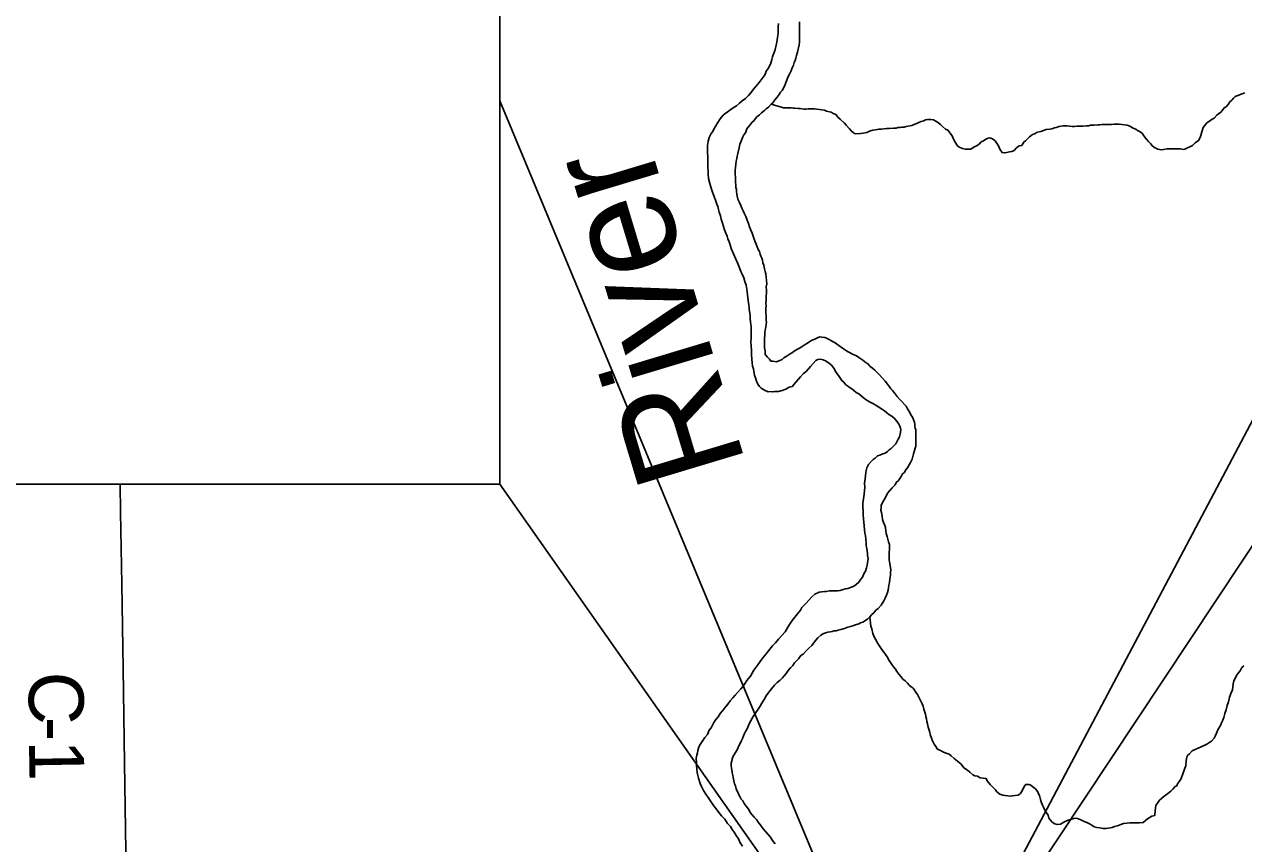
# Model space of a CAD drawing. Extents: x 0 to 34, y 0 to 22.
# Drawn here: x 5.328 to 6.59, y 17.212 to 18.059 of the extents above; entities that cross this region are included whole.
import ezdxf

# ---------------------------------------------------------------- set-up
doc = ezdxf.new("R2010")
doc.units = 0
for name, color, linetype in [('GM_X_County_Road', 7, 'Continuous'), ('GM_X_County_Road_Text', 7, 'Continuous'), ('GM_X_Major_River', 7, 'Continuous'), ('GM_X_Major_River_Text', 7, 'Continuous'), ('GM_X_Minor_River', 7, 'Continuous'), ('SH_Border', 7, 'Continuous')]:
    doc.layers.add(name, color=color, linetype=linetype)

msp = doc.modelspace()

# ---------------------------------------------------------------- linework, layer by layer
at = {"layer": 'GM_X_County_Road'}
msp.add_lwpolyline([(5.4268, 17.5835), (5.4273, 17.5548), (5.4287, 17.4801), (5.4301, 17.393), (5.4313, 17.2951), (5.4329, 17.2045), (5.4343, 17.1322), (5.4347, 17.045), (5.4352, 17.0104)], dxfattribs=at)
at = {"layer": 'GM_X_Major_River'}
for points in [[(6.1082, 18.06), (6.1079, 18.0569), (6.108, 18.0535), (6.108, 18.0504), (6.1077, 18.0478), (6.1074, 18.0455), (6.107, 18.0432), (6.1067, 18.0409), (6.106, 18.0375), (6.105, 18.0333), (6.1039, 18.0302), (6.1028, 18.0275), (6.1021, 18.0256), (6.1014, 18.0229), (6.1003, 18.0191), (6.0985, 18.0153), (6.097, 18.0126), (6.0956, 18.0107), (6.0949, 18.0084), (6.0934, 18.006), (6.0915, 18.0033), (6.0893, 18.0006), (6.0871, 17.9972), (6.0845, 17.9945), (6.0826, 17.9921), (6.0808, 17.9898), (6.0793, 17.9879), (6.0771, 17.9856), (6.0741, 17.9824), (6.0707, 17.9801), (6.0681, 17.9778), (6.0648, 17.975), (6.0614, 17.9727), (6.0528, 17.9668), (6.0509, 17.9652), (6.0479, 17.9614), (6.045, 17.9567), (6.0435, 17.9544), (6.042, 17.9521), (6.0402, 17.9483), (6.0387, 17.9463), (6.0376, 17.9444), (6.0365, 17.9421), (6.0355, 17.9383), (6.0351, 17.9364), (6.0348, 17.9337), (6.0349, 17.9311), (6.0349, 17.9288), (6.035, 17.9261), (6.0351, 17.9227), (6.0351, 17.9197), (6.0352, 17.9166)], [(6.0959, 17.7811), (6.0958, 17.7842), (6.0957, 17.7876), (6.0961, 17.791), (6.0955, 17.7978), (6.0951, 17.8012), (6.0946, 17.8035), (6.0938, 17.8065), (6.093, 17.8103), (6.0922, 17.8126), (6.0917, 17.8152), (6.0909, 17.8175), (6.0901, 17.8194), (6.0893, 17.8216), (6.0885, 17.8243), (6.0873, 17.8265), (6.0861, 17.8292), (6.0853, 17.8318), (6.0841, 17.8341), (6.0833, 17.8371), (6.0821, 17.8401), (6.0809, 17.8431), (6.0797, 17.8465), (6.0784, 17.8499), (6.0772, 17.8533), (6.076, 17.8567), (6.0744, 17.8605), (6.0728, 17.8639), (6.0716, 17.8665), (6.0704, 17.8691), (6.0692, 17.8718), (6.0676, 17.8755), (6.0664, 17.8785), (6.0656, 17.8816), (6.0652, 17.8838), (6.0647, 17.8861), (6.0647, 17.8884), (6.0643, 17.8903), (6.0642, 17.8937), (6.0638, 17.8956), (6.0637, 17.8979), (6.0637, 17.9013), (6.0636, 17.9039), (6.0636, 17.9062), (6.0635, 17.9081), (6.0638, 17.9115), (6.0641, 17.9146), (6.0645, 17.9176), (6.0652, 17.9203), (6.0655, 17.923), (6.0662, 17.9257), (6.0676, 17.9314), (6.0683, 17.9352), (6.0697, 17.9383), (6.0708, 17.941), (6.0715, 17.9429), (6.0726, 17.9448), (6.0741, 17.9471), (6.0755, 17.9513), (6.0785, 17.9548), (6.0811, 17.9579), (6.083, 17.9598), (6.0844, 17.9618), (6.0859, 17.9637), (6.0885, 17.9657), (6.0908, 17.9676), (6.0938, 17.97), (6.0956, 17.9719), (6.0979, 17.9735), (6.1009, 17.9766), (6.1027, 17.9785), (6.1046, 17.9812), (6.1068, 17.9839), (6.109, 17.9866), (6.1105, 17.9889), (6.112, 17.9909), (6.1138, 17.994), (6.1153, 17.997), (6.116, 17.9989), (6.1171, 18.0016), (6.1181, 18.0047), (6.1196, 18.0078), (6.1211, 18.0104), (6.1221, 18.0131), (6.1229, 18.015), (6.124, 18.017), (6.1247, 18.0197), (6.1254, 18.0219), (6.1261, 18.0242), (6.1268, 18.0269), (6.1279, 18.0304), (6.1296, 18.038), (6.1299, 18.0407), (6.1302, 18.0445), (6.1301, 18.0483), (6.13, 18.0528), (6.13, 18.0559), (6.1299, 18.0589), (6.1299, 18.0619)], [(6.0352, 17.9166), (6.0352, 17.9136), (6.0353, 17.9109), (6.0354, 17.9075), (6.0354, 17.9041), (6.0359, 17.8999), (6.0372, 17.8946), (6.0388, 17.8897), (6.04, 17.8856), (6.0416, 17.881), (6.0433, 17.8765), (6.0445, 17.8731), (6.0457, 17.8709), (6.0461, 17.8678), (6.0469, 17.8648), (6.0482, 17.861), (6.049, 17.8576), (6.0502, 17.8535), (6.0514, 17.8501), (6.0526, 17.8467), (6.0539, 17.8433), (6.0551, 17.8403), (6.0559, 17.8373), (6.0571, 17.8342), (6.0583, 17.8312), (6.0595, 17.8275), (6.0643, 17.8165), (6.0659, 17.8124), (6.0679, 17.8075), (6.0695, 17.8037), (6.0707, 17.8007), (6.0723, 17.797), (6.0736, 17.7932), (6.0748, 17.7894), (6.0756, 17.7852), (6.0761, 17.7796), (6.077, 17.7731), (6.0775, 17.7693), (6.078, 17.7652), (6.0784, 17.7621), (6.0789, 17.7583), (6.0789, 17.7549), (6.0794, 17.7511), (6.0799, 17.747), (6.08, 17.7428), (6.0801, 17.7386), (6.0801, 17.7348), (6.0798, 17.7314), (6.0799, 17.7261), (6.0804, 17.7223), (6.0805, 17.7173), (6.0806, 17.7128), (6.0811, 17.709), (6.0815, 17.7056), (6.0823, 17.7029), (6.0828, 17.7003), (6.0836, 17.6965), (6.0848, 17.6927), (6.0856, 17.6901), (6.0869, 17.6871), (6.0888, 17.6848), (6.0904, 17.683), (6.0938, 17.6808), (6.0977, 17.6793), (6.1003, 17.6794), (6.1022, 17.679), (6.1045, 17.6795), (6.1083, 17.6795), (6.1121, 17.6804), (6.1159, 17.682), (6.1193, 17.684), (6.1227, 17.6848), (6.1241, 17.6867), (6.1312, 17.6945), (6.1342, 17.698), (6.1368, 17.7003), (6.1394, 17.703), (6.1416, 17.7053), (6.1442, 17.7084), (6.1468, 17.7115), (6.1491, 17.7127), (6.1517, 17.7128), (6.1544, 17.7121), (6.1575, 17.711), (6.161, 17.7084), (6.1633, 17.7066), (6.1656, 17.7036), (6.168, 17.6991), (6.1704, 17.6961), (6.1719, 17.6938), (6.1739, 17.6908), (6.1758, 17.689), (6.1778, 17.6868), (6.1797, 17.6853), (6.1816, 17.6838), (6.1843, 17.6823), (6.1863, 17.6805), (6.1886, 17.6786), (6.1913, 17.6772), (6.1936, 17.6753), (6.1963, 17.6731)], [(6.2492, 17.6184), (6.2496, 17.621), (6.2503, 17.623), (6.2506, 17.6271), (6.2505, 17.6302), (6.2504, 17.6336), (6.2504, 17.637), (6.2503, 17.6397), (6.2499, 17.6416), (6.2495, 17.6435), (6.2494, 17.6454), (6.249, 17.6476), (6.247, 17.6529), (6.2454, 17.6555), (6.2442, 17.6578), (6.2426, 17.6604), (6.2414, 17.6623), (6.2403, 17.6642), (6.2387, 17.666), (6.236, 17.669), (6.234, 17.6712), (6.2313, 17.6742), (6.229, 17.6772), (6.2262, 17.6806), (6.2247, 17.6824), (6.2231, 17.6843), (6.2211, 17.6869), (6.2188, 17.6903), (6.2157, 17.6937), (6.2122, 17.6974), (6.2102, 17.6996), (6.2079, 17.7015), (6.2056, 17.7037), (6.2032, 17.7055), (6.2009, 17.7082), (6.1978, 17.71), (6.1955, 17.7118), (6.1936, 17.7133), (6.1913, 17.7148), (6.1889, 17.7163), (6.1866, 17.7173), (6.1843, 17.7184), (6.1824, 17.7195), (6.1805, 17.7206), (6.1786, 17.7217), (6.1747, 17.7243), (6.172, 17.7261), (6.167, 17.7298), (6.165, 17.7309), (6.1631, 17.732), (6.1608, 17.7331), (6.1581, 17.7346), (6.1562, 17.7353), (6.1535, 17.7356), (6.1512, 17.736), (6.1486, 17.7351), (6.146, 17.7336), (6.1437, 17.7328), (6.1418, 17.732), (6.1384, 17.7296), (6.1358, 17.728), (6.1339, 17.7268), (6.1306, 17.7245), (6.1279, 17.7233), (6.1245, 17.7213), (6.1227, 17.7198), (6.1204, 17.7186), (6.1174, 17.7162), (6.114, 17.7143), (6.1122, 17.7127), (6.1088, 17.7111), (6.1061, 17.7103), (6.1023, 17.711), (6.1004, 17.7109), (6.0989, 17.7128), (6.0969, 17.715), (6.0946, 17.7176), (6.0945, 17.7214), (6.094, 17.7248), (6.094, 17.7275), (6.0939, 17.7309), (6.0939, 17.7332), (6.0938, 17.7351), (6.0942, 17.7374), (6.0941, 17.7404), (6.0944, 17.7427), (6.0948, 17.7446), (6.0951, 17.7465), (6.0954, 17.7492), (6.0958, 17.7511), (6.0957, 17.753), (6.0957, 17.7553), (6.0956, 17.7579), (6.0952, 17.7606), (6.0951, 17.7629), (6.0951, 17.7655), (6.0954, 17.7682), (6.0953, 17.7709), (6.0957, 17.7739), (6.0956, 17.7785), (6.0959, 17.7811)], [(6.1963, 17.6731), (6.2002, 17.6701), (6.2033, 17.6683), (6.206, 17.6672), (6.2083, 17.6658), (6.216, 17.661), (6.2179, 17.6595), (6.2202, 17.6576), (6.2226, 17.6558), (6.2256, 17.654), (6.2284, 17.6517), (6.2307, 17.6488), (6.2327, 17.6458), (6.2339, 17.6435), (6.2347, 17.6416), (6.2351, 17.6397), (6.2344, 17.6355), (6.2337, 17.6325), (6.2322, 17.6302), (6.2311, 17.6282), (6.2297, 17.6252), (6.2271, 17.6225), (6.2248, 17.6205), (6.223, 17.6193), (6.2211, 17.6174), (6.2188, 17.6158), (6.2162, 17.615), (6.2132, 17.6138), (6.2109, 17.613), (6.2083, 17.6106), (6.2064, 17.6091), (6.2042, 17.6071), (6.2016, 17.604), (6.1998, 17.6006), (6.1991, 17.5979), (6.1987, 17.5956), (6.1984, 17.5926), (6.1981, 17.5888), (6.1974, 17.5849), (6.1975, 17.5804), (6.1969, 17.5732), (6.1963, 17.5686), (6.1956, 17.564), (6.1957, 17.5598), (6.1958, 17.556), (6.1959, 17.5515), (6.1973, 17.5367), (6.1978, 17.5329), (6.1982, 17.5302), (6.1987, 17.5268), (6.1991, 17.5227), (6.1992, 17.52), (6.1996, 17.517), (6.2001, 17.5147), (6.2005, 17.5117), (6.2006, 17.5098), (6.201, 17.5067), (6.2007, 17.5045), (6.2003, 17.5022), (6.2, 17.4999), (6.1993, 17.4972), (6.1982, 17.4938), (6.1971, 17.4915), (6.1953, 17.4876), (6.1935, 17.4853), (6.1916, 17.4822), (6.1886, 17.4799), (6.1864, 17.4783), (6.1838, 17.4771), (6.1819, 17.4763), (6.18, 17.4759), (6.1777, 17.4754), (6.1754, 17.4746), (6.172, 17.4738), (6.1694, 17.4734), (6.1667, 17.4733), (6.1648, 17.4733), (6.1629, 17.4732), (6.161, 17.4732), (6.158, 17.4727), (6.1561, 17.4727), (6.153, 17.4723), (6.1504, 17.4718), (6.1459, 17.4698), (6.1429, 17.4671), (6.1399, 17.464), (6.1366, 17.4601), (6.1343, 17.4578), (6.1325, 17.4562), (6.131, 17.4532), (6.128, 17.4497), (6.1251, 17.4462), (6.1225, 17.4427), (6.1203, 17.4396), (6.1181, 17.4358), (6.1151, 17.4311), (6.1118, 17.4273), (6.1084, 17.4234), (6.1051, 17.4195), (6.1021, 17.4164), (6.0992, 17.4129)], [(6.1071, 17.3785), (6.1101, 17.3809), (6.1123, 17.3832), (6.1142, 17.3855), (6.1164, 17.3879), (6.1183, 17.3909), (6.1209, 17.3937), (6.1231, 17.396), (6.1249, 17.3987), (6.1272, 17.4014), (6.129, 17.4029), (6.1316, 17.4064), (6.1339, 17.408), (6.1376, 17.4119), (6.1398, 17.4142), (6.1428, 17.4169), (6.1447, 17.4192), (6.1469, 17.4223), (6.1491, 17.4247), (6.1521, 17.4274), (6.1547, 17.429), (6.157, 17.4298), (6.1593, 17.4306), (6.1619, 17.431), (6.1638, 17.4314), (6.1657, 17.4319), (6.168, 17.4319), (6.1699, 17.4327), (6.1729, 17.4335), (6.1767, 17.4344), (6.1801, 17.4356), (6.1827, 17.4364), (6.1854, 17.4372), (6.188, 17.438), (6.1914, 17.4393), (6.1933, 17.4401), (6.1956, 17.4409), (6.2004, 17.444), (6.2027, 17.4463), (6.2049, 17.4487), (6.2071, 17.4506), (6.209, 17.4533), (6.2116, 17.4549), (6.2146, 17.4584), (6.2172, 17.463), (6.2186, 17.4657), (6.2201, 17.4688), (6.2212, 17.4715), (6.2219, 17.4741), (6.2222, 17.4764), (6.2225, 17.4791), (6.2232, 17.4821), (6.2235, 17.4856), (6.2242, 17.4894), (6.2241, 17.4924), (6.2245, 17.4951), (6.2244, 17.4974), (6.224, 17.4993), (6.2236, 17.5015), (6.2231, 17.5034), (6.2227, 17.5053), (6.2227, 17.5076), (6.223, 17.511), (6.2229, 17.5137), (6.2233, 17.5156), (6.2232, 17.5182), (6.2231, 17.5213), (6.2223, 17.5239), (6.2215, 17.5269), (6.2207, 17.5296), (6.2199, 17.5326), (6.2194, 17.5353), (6.219, 17.5387), (6.2182, 17.5409), (6.217, 17.5439), (6.2161, 17.547), (6.2157, 17.5504), (6.2148, 17.5542), (6.2144, 17.5568), (6.2147, 17.5591), (6.2147, 17.5621), (6.2169, 17.5664), (6.2187, 17.5691), (6.2212, 17.5744), (6.2235, 17.5772), (6.2261, 17.5799), (6.2291, 17.583), (6.2301, 17.5853), (6.2324, 17.5876), (6.2339, 17.5895), (6.2353, 17.5915), (6.2368, 17.5942), (6.2387, 17.5957), (6.2398, 17.598), (6.242, 17.6007), (6.2435, 17.6038), (6.2449, 17.6061), (6.2468, 17.6096), (6.2475, 17.6123), (6.2482, 17.6149), (6.2492, 17.6184)], [(6.0992, 17.4129), (6.0954, 17.4083), (6.0921, 17.404), (6.0892, 17.4002), (6.0869, 17.3967), (6.0847, 17.394), (6.0829, 17.3913), (6.081, 17.3882), (6.0792, 17.3851), (6.0773, 17.3828), (6.0755, 17.3805), (6.0737, 17.3778), (6.0718, 17.3747), (6.0692, 17.372), (6.0662, 17.3685), (6.0633, 17.3654), (6.061, 17.3627), (6.0584, 17.3596), (6.0559, 17.3561), (6.0529, 17.3523), (6.0503, 17.3492), (6.0481, 17.3465), (6.0459, 17.343), (6.0436, 17.3403), (6.0414, 17.3372), (6.0385, 17.3318), (6.0366, 17.3291), (6.0348, 17.3249), (6.0322, 17.3218), (6.0267, 17.3133), (6.0256, 17.3106), (6.0249, 17.3083), (6.0246, 17.3057), (6.0239, 17.3034), (6.0232, 17.3003), (6.0233, 17.2961), (6.0233, 17.2927), (6.0238, 17.2889), (6.0243, 17.2855), (6.0247, 17.2825), (6.0255, 17.2795), (6.0272, 17.2742), (6.0288, 17.2708), (6.0307, 17.2667), (6.0331, 17.2629), (6.0355, 17.2595), (6.0382, 17.2554), (6.041, 17.2513), (6.0437, 17.2479), (6.0464, 17.2442), (6.0492, 17.2408), (6.0527, 17.2371), (6.0554, 17.2326), (6.0585, 17.2296), (6.0605, 17.2266), (6.0625, 17.2236), (6.0644, 17.2203), (6.0668, 17.2169), (6.0688, 17.2128), (6.0711, 17.2094)], [(6.105, 17.2116), (6.1022, 17.215), (6.0999, 17.2184), (6.0924, 17.2273), (6.0901, 17.2307), (6.0874, 17.2341), (6.0854, 17.2367), (6.0831, 17.2393), (6.0811, 17.2415), (6.0795, 17.2438), (6.0772, 17.2475), (6.0748, 17.2505), (6.0729, 17.2535), (6.0713, 17.2561), (6.0697, 17.258), (6.0682, 17.2606), (6.0674, 17.2625), (6.0666, 17.2644), (6.0654, 17.2663), (6.0646, 17.2685), (6.0637, 17.2716), (6.0629, 17.2738), (6.0621, 17.2768), (6.0617, 17.2787), (6.0613, 17.281), (6.0608, 17.2837), (6.0604, 17.2859), (6.06, 17.2882), (6.0595, 17.292), (6.0594, 17.295), (6.0612, 17.3015), (6.0638, 17.3061), (6.066, 17.3096), (6.0674, 17.3131), (6.0689, 17.3161), (6.07, 17.3184), (6.0711, 17.3207), (6.0721, 17.3234), (6.0732, 17.3257), (6.0743, 17.328), (6.0758, 17.3307), (6.0772, 17.3342), (6.0794, 17.3384), (6.082, 17.3434), (6.0894, 17.3542), (6.0912, 17.3573), (6.0934, 17.3611), (6.0956, 17.3646), (6.0982, 17.3685), (6.1012, 17.3719), (6.1041, 17.3758), (6.1071, 17.3785)]]:
    msp.add_lwpolyline(points, dxfattribs=at)
at = {"layer": 'GM_X_Minor_River'}
for points in [[(6.3641, 17.9386), (6.3682, 17.9428), (6.3712, 17.9452), (6.3735, 17.946), (6.3754, 17.9472), (6.378, 17.948), (6.3799, 17.9484), (6.3852, 17.9504), (6.389, 17.9509), (6.3913, 17.9513), (6.3939, 17.9521), (6.3958, 17.9526), (6.3988, 17.9534), (6.403, 17.9542), (6.4049, 17.9543), (6.4072, 17.9543), (6.4095, 17.954), (6.4121, 17.9537), (6.4148, 17.9537), (6.4171, 17.9538), (6.4197, 17.9538), (6.4232, 17.9539), (6.427, 17.9544), (6.4292, 17.9544), (6.4311, 17.9549), (6.433, 17.9549), (6.4349, 17.9549), (6.4387, 17.9554), (6.441, 17.9554), (6.4429, 17.9555), (6.4452, 17.9555), (6.4471, 17.9556), (6.4498, 17.9556), (6.4528, 17.9557), (6.4558, 17.9558), (6.4585, 17.9558), (6.4608, 17.9559), (6.4638, 17.9556), (6.4692, 17.9549), (6.4719, 17.9538), (6.4753, 17.952), (6.478, 17.9509), (6.4799, 17.9494), (6.4819, 17.9484), (6.4846, 17.9465), (6.4865, 17.9439), (6.4889, 17.9409), (6.4912, 17.9379), (6.4935, 17.9357), (6.4951, 17.9334), (6.4974, 17.932), (6.5009, 17.9301), (6.5028, 17.9298), (6.5051, 17.9295), (6.507, 17.9299), (6.5104, 17.9303), (6.5131, 17.9304), (6.5153, 17.9305), (6.5172, 17.9305), (6.5191, 17.9305), (6.5218, 17.9306), (6.5245, 17.9303), (6.5271, 17.9299), (6.529, 17.93), (6.5369, 17.934), (6.5396, 17.9367), (6.5429, 17.939), (6.5448, 17.9421), (6.5455, 17.9444), (6.5465, 17.9479), (6.548, 17.9524), (6.5491, 17.9544), (6.5517, 17.9575), (6.5543, 17.959), (6.5573, 17.961), (6.5592, 17.9622), (6.5621, 17.9653), (6.564, 17.9669), (6.5659, 17.968), (6.5681, 17.9707), (6.5696, 17.9727), (6.5715, 17.9739), (6.5737, 17.9762), (6.5756, 17.9789), (6.5774, 17.9808), (6.5793, 17.9828), (6.5811, 17.9847), (6.591, 17.9883)], [(6.1009, 17.9766), (6.1135, 17.973), (6.1173, 17.9727), (6.1215, 17.9728), (6.1234, 17.9725), (6.1253, 17.9725), (6.1283, 17.9722), (6.1306, 17.9723), (6.1329, 17.9719), (6.1348, 17.9716), (6.1367, 17.9716), (6.1386, 17.9717), (6.1424, 17.9718), (6.1455, 17.9718), (6.1481, 17.9715), (6.1508, 17.9712), (6.1531, 17.9709), (6.1561, 17.9705), (6.1581, 17.9694), (6.1611, 17.9688), (6.163, 17.9684), (6.165, 17.9669), (6.1677, 17.9659), (6.17, 17.9629), (6.1723, 17.961), (6.1766, 17.9569), (6.1785, 17.9551), (6.1817, 17.9513), (6.1836, 17.9491), (6.1856, 17.9472), (6.1875, 17.9458), (6.1932, 17.9463), (6.1958, 17.9467), (6.1996, 17.9475), (6.2026, 17.9488), (6.206, 17.9496), (6.2083, 17.95), (6.2106, 17.9504), (6.2125, 17.9509), (6.2148, 17.9509), (6.2174, 17.951), (6.2201, 17.9514), (6.2227, 17.9515), (6.2273, 17.952), (6.23, 17.952), (6.2319, 17.9524), (6.2341, 17.9525), (6.236, 17.9529), (6.2383, 17.9529), (6.2406, 17.9534), (6.2444, 17.9542), (6.2463, 17.9546), (6.2493, 17.9558), (6.2523, 17.9571), (6.2542, 17.9579), (6.2561, 17.9587), (6.2587, 17.9595), (6.2606, 17.9603), (6.2625, 17.9607), (6.2659, 17.9608), (6.2686, 17.9604), (6.2728, 17.9579), (6.2759, 17.9557), (6.2782, 17.9534), (6.2813, 17.9508), (6.2836, 17.9498), (6.2848, 17.9479), (6.2868, 17.9456), (6.288, 17.9438), (6.2895, 17.9404), (6.2911, 17.9374), (6.2935, 17.9336), (6.2954, 17.9321), (6.2989, 17.9307), (6.3016, 17.93), (6.3035, 17.93), (6.3073, 17.9301), (6.3099, 17.9317), (6.3133, 17.9337), (6.3159, 17.9353), (6.3181, 17.9376), (6.3204, 17.9388), (6.323, 17.9403), (6.3253, 17.9415), (6.3272, 17.942), (6.3299, 17.9409), (6.3326, 17.9387), (6.3353, 17.9345), (6.3365, 17.9327), (6.3373, 17.93), (6.3397, 17.9266), (6.342, 17.9263), (6.3446, 17.9268), (6.3473, 17.9272), (6.3499, 17.9276), (6.3522, 17.9288), (6.3548, 17.9315), (6.3574, 17.9335), (6.3601, 17.9339), (6.3623, 17.9374), (6.3641, 17.9386)], [(6.2027, 17.4463), (6.204, 17.4369), (6.2048, 17.4339), (6.2061, 17.4293), (6.2073, 17.4259), (6.2089, 17.4225), (6.2112, 17.4188), (6.2132, 17.4158), (6.2152, 17.4128), (6.2171, 17.4102), (6.2187, 17.4083), (6.2199, 17.4064), (6.2211, 17.4046), (6.2222, 17.4023), (6.225, 17.3982), (6.2274, 17.3948), (6.2293, 17.3922), (6.2309, 17.39), (6.2328, 17.3873), (6.2352, 17.3843), (6.2371, 17.3821), (6.2395, 17.3803), (6.2418, 17.378), (6.2437, 17.3758), (6.2457, 17.3739), (6.2476, 17.3725), (6.2504, 17.3687), (6.2523, 17.3661), (6.2571, 17.3563), (6.2579, 17.3541), (6.2587, 17.351), (6.2595, 17.3488), (6.2604, 17.3458), (6.2608, 17.3435), (6.2616, 17.3408), (6.262, 17.3382), (6.2625, 17.3359), (6.2633, 17.3325), (6.2641, 17.3291), (6.2649, 17.3268), (6.2654, 17.3246), (6.2666, 17.3208), (6.2678, 17.3182), (6.2694, 17.3148), (6.271, 17.3122), (6.2725, 17.3099), (6.2744, 17.3088), (6.2768, 17.3077), (6.2791, 17.3066), (6.2817, 17.3055), (6.2848, 17.3045), (6.2871, 17.3026), (6.2902, 17.3), (6.2937, 17.2971), (6.2972, 17.2941), (6.3003, 17.2904), (6.3038, 17.2878), (6.3065, 17.2859), (6.3096, 17.283), (6.3115, 17.2819), (6.3142, 17.2815), (6.3169, 17.2801), (6.3234, 17.2791), (6.3242, 17.2768), (6.3273, 17.2731), (6.3304, 17.2701), (6.3328, 17.2675), (6.3343, 17.2656), (6.3374, 17.2631), (6.3405, 17.262), (6.3428, 17.2616), (6.3458, 17.2613), (6.3485, 17.261), (6.3504, 17.2614), (6.3531, 17.2615), (6.3565, 17.2619), (6.3583, 17.2635), (6.3606, 17.2666), (6.3627, 17.2708), (6.3642, 17.2731), (6.3673, 17.2732), (6.3696, 17.2725), (6.3715, 17.2706), (6.3742, 17.2684), (6.3766, 17.2654), (6.3774, 17.2635), (6.3785, 17.2617), (6.3794, 17.2575), (6.3806, 17.2541), (6.3814, 17.2515), (6.3826, 17.2496), (6.3838, 17.2466), (6.3858, 17.2436), (6.3873, 17.2413), (6.3882, 17.2383), (6.3917, 17.2342), (6.3944, 17.2324), (6.3967, 17.2317)], [(6.3967, 17.2317), (6.4001, 17.2321), (6.4035, 17.2341), (6.4065, 17.2353), (6.4091, 17.2365), (6.4129, 17.2377), (6.4152, 17.2381), (6.4178, 17.2378), (6.4213, 17.2364), (6.4248, 17.2349), (6.4274, 17.2338), (6.4301, 17.2324), (6.4325, 17.2309), (6.4351, 17.2294), (6.4378, 17.2287), (6.4409, 17.2281), (6.4443, 17.2277), (6.4474, 17.2274), (6.4493, 17.2279), (6.4519, 17.2283), (6.4538, 17.2287), (6.4561, 17.2295), (6.4591, 17.2303), (6.4625, 17.2316), (6.4655, 17.2328), (6.4689, 17.2332), (6.472, 17.2333), (6.4754, 17.2334), (6.4788, 17.2334), (6.4818, 17.2335), (6.4856, 17.2336), (6.4901, 17.2375), (6.4946, 17.2402), (6.4977, 17.2411), (6.4983, 17.246), (6.499, 17.2514), (6.5027, 17.2568), (6.5071, 17.2607), (6.5113, 17.2638), (6.5142, 17.2661), (6.5165, 17.2681), (6.5187, 17.2708), (6.5206, 17.2716), (6.5213, 17.2739), (6.5232, 17.2766), (6.5246, 17.2785), (6.5254, 17.2804), (6.5264, 17.2831), (6.5272, 17.285), (6.5279, 17.2869), (6.529, 17.29), (6.53, 17.2923), (6.5303, 17.298), (6.5314, 17.3026), (6.5336, 17.3049), (6.5366, 17.3077), (6.5403, 17.3096), (6.5434, 17.3108), (6.5452, 17.3116), (6.5471, 17.3128), (6.5494, 17.3136), (6.5516, 17.3148), (6.5546, 17.3168), (6.5565, 17.318), (6.5591, 17.3211), (6.5602, 17.323), (6.5617, 17.3261), (6.5635, 17.3303), (6.5657, 17.3341), (6.5668, 17.3368), (6.5682, 17.3395), (6.5693, 17.3422), (6.5704, 17.3464), (6.5718, 17.3502), (6.5728, 17.3548), (6.5739, 17.3586), (6.575, 17.3632), (6.5768, 17.3678), (6.5782, 17.3709), (6.5788, 17.377), (6.5795, 17.3804), (6.581, 17.3827), (6.5828, 17.3866), (6.5847, 17.3889), (6.5865, 17.3912), (6.588, 17.3939), (6.5899, 17.3958)]]:
    msp.add_lwpolyline(points, dxfattribs=at)
at = {"layer": 'SH_Border'}
for points in [[(6.9977, 18.4031), (6.2611, 17.0116), (6.9977, 18.1206)], [(3.7168, 18.3764), (5.8199, 18.3764), (5.8199, 17.5835), (3.7168, 17.5835)], [(5.8199, 17.98), (6.2246, 17.0078), (5.8199, 17.5835)]]:
    msp.add_lwpolyline(points, close=True, dxfattribs=at)

# ---------------------------------------------------------------- texts
at = {"layer": 'GM_X_County_Road_Text'}
for s, rotation, p in [('C', 270.0117, (5.3324, 17.3897)), ('-', 270.1544, (5.3324, 17.3429)), ('1', 271.0014, (5.3325, 17.3186))]:
    msp.add_text(s, height=0.0568, rotation=rotation, dxfattribs=at).set_placement(p)
at = {"layer": 'GM_X_Major_River_Text'}
msp.add_text('River', height=0.11371, rotation=106.7513, dxfattribs=at).set_placement((6.0751, 17.6039))

doc.saveas('drawing.dxf')
